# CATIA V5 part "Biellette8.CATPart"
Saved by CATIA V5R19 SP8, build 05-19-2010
Part number: Biellette8
Bounding box of the stored display mesh (mm): x -126 to -100, y 43.616 to 101.759, z -52.469 to -23.746
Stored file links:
  G:\EU_thinkMotion\CFAO_2010\MMS_groupe2\MMS_groupe2\A reprendre\jcauchy\Biellette8.CATPart
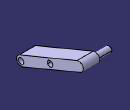
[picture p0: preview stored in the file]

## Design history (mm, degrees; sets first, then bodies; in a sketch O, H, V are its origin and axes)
Parameters
  Rayonfixation_biellette8 = 2.5 mm
  Longueurbiellette_biellette8 = 54.364 mm
  Largeurbiellette_biellette8 = 8 mm
  Hauteurbiellette8_biellette8 = 14 mm
Set1
  Plane1: stored without definition
  Sketch1 on Plane1, origin (-100, 0, 0), H (0, 1, 0), V (0, 0, 1)
    line L1 (46.062, -44.886) -> (96.2317, -23.9468)
    point P1 (46.062, -44.886)
    point P2 (96.2317, -23.9468)
    arc A1 centre (97.7723, -27.6382) radius 4 from (99.313, -31.3296) to (96.2317, -23.9468) ccw
    point P5 (96.2317, -23.9468)
    line L2 (99.313, -31.3296) -> (49.1433, -52.2688)
    arc A2 centre (47.6027, -48.5774) radius 4 from (46.062, -44.886) to (49.1433, -52.2688) ccw
    point P8 (46.062, -44.886)
    distance L2 L1 = 8 {= Largeurbiellette_biellette8}
    length L1 = 54.364 {= Longueurbiellette_biellette8}
    tangency: A1 L1, L2 A1, A2 L2, L1 A2
    coincidence: P5 P2, P1 P8
  Point1: stored without definition
  DatumPoint1
  Point2: stored without definition
  DatumPoint2
Body1 (main body)
  Pad1: profile Sketch1, direction (-1, 0, 0), length 14 {= Hauteurbiellette8_biellette8}
  Sketch2 on start face of Pad1, origin (-100, 0, 0), H (0, 1, 0), V (0, 0, 1)
    circle A1 centre (97.7723, -27.6382) radius 2.5
    point P1 (97.7723, -27.6382)
    reference projected arc E1 centre (97.7723, -27.6382) radius 4 from (99.313, -31.3296) to (96.2317, -23.9468) ccw from edge [face of Pad1 from Sketch1.A1 | start face of Pad1]
    radius A1 = 2.5 {= Rayonfixation_biellette8}
    distance P1 E1 = 4 {= Largeurbiellette_biellette8 /2}
  Pad2: profile Sketch2, direction (-1, 0, 0), length 26
  Sketch3 on face of Pad2, origin (-100, 47.6027, -48.5774), H (0, 1, 0), V (0, 0, 1)
    point P1 (0, 0)
    reference projected arc E1 centre (0, 0) radius 4 from (-1.5407, 3.6914) to (1.5407, -3.6914) ccw from edge [face of Pad1 from Sketch1.A2 | start face of Pad1]
    distance P1 E1 = 4 {= Largeurbiellette_biellette8 /2}
  Hole1: placed by Sketch3, at (-100, 47.6027, -48.5774) direction (-1, 0, 0), diameter 5 {= Rayonfixation_biellette8*2}, through (limit type 6)
  Sketch4 on end face of Pad1, origin (-114, 84.5821, -31.9504), H (0, 1, 0), V (0, 0, -1)
    point P1 (-11.8946, 6.1574)
    reference projected line E1 (-35.4387, 20.3184) -> (14.7309, -0.6208) from edge [end face of Pad1 | face of Pad1 from Sketch1.L2]
    reference projected arc E2 centre (13.1902, -4.3122) radius 4 from (11.6496, -8.0036) to (14.7309, -0.6208) ccw from edge [end face of Pad1 | face of Pad1 from Sketch1.A1]
    distance P1 E1 = 4 {= Largeurbiellette_biellette8 /2}
    distance P1 E2 = 31.182 {= Longueurbiellette_biellette8 /2+Largeurbiellette_biellette8 /2}
  Hole2: placed by Sketch4, at (-114, 72.6875, -38.1078) direction (1, 0, 0), diameter 5 {= Rayonfixation_biellette8 *2}, through (limit type 6)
